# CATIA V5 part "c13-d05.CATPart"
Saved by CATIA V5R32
Part number: Part1
Bounding box of the stored display mesh (mm): x -62.5 to 62.5, y -75 to 75, z 0 to 20
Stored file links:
  D:\PROJECTS\Project 2022\CATIA V5 6R 2022\Resources\Part Files\c13_catia_v5_6r2022_prt\c13_catia_v5-6r2022_figr_13-28\c13-d05.CATPart
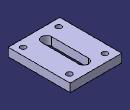
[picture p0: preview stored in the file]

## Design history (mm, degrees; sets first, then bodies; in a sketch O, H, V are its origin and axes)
Body1 (main body)
  Sketch1 on xy-plane, origin (0, 0, 0), H (1, 0, 0), V (0, 1, 0)
    line L1 (62.5, 75) -> (62.5, -75)
    line L2 (62.5, -75) -> (-62.5, -75)
    line L3 (-62.5, -75) -> (-62.5, 75)
    line L4 (-62.5, 75) -> (62.5, 75)
    length L1 = 150
    length L2 = 125
    vertical: L1 V, L3 V
    horizontal: L2 H, L4 H
    equidistance: L1 L3 O, L2 L4 O
  Pad1: profile Sketch1, direction (0, 0, 1), length 20
  Sketch2 on face of Pad1, origin (0, 0, 20), H (1, 0, 0), V (0, 1, 0)
    construction line L1 (0, 45) -> (0, -45)
    point P1 (0, 45)
    line L2 (12, 45) -> (12, -45)
    line L3 (-12, -45) -> (-12, 45)
    arc A1 centre (0, -45) radius 12 from (12, -45) to (-12, -45) cw
    arc A2 centre (0, 45) radius 12 from (-12, 45) to (12, 45) cw
    length L1 = 90
    radius A2 = 12
    coincidence: P1 V
    vertical: L1 V
    tangency: A1 L2, A2 L2, A1 L3, A2 L3
    parallelism: L1 L2
    midpoint: O L1
  Pocket1: profile Sketch2, direction (0, 0, -1), through (limit type 3)
  Sketch3 on face of Pad1, origin (38.7626, -18.4621, 20), H (1, 0, 0), V (0, 1, 0)
    point P1 (5.7374, -38.5379)
    reference projected line E1 (-101.2626, -56.5379) -> (23.7374, -56.5379) from edge [face of Pad1 | face of Pad1]
    reference projected line E2 (23.7374, -56.5379) -> (23.7374, 93.4621) from edge [face of Pad1 | face of Pad1]
    distance P1 E1 = 18
    distance P1 E2 = 18
  Hole1: placed by Sketch3, at (44.5, -57, 20) direction (0, 0, -1), diameter 13, through (limit type 3)
  RectPattern1: of Hole1, direction 1 instances 2, spacing 86, along edge [face of Pad1 | face of Pad1] reversed, direction 2 instances 2, spacing 112, along edge [face of Pad1 | face of Pad1]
